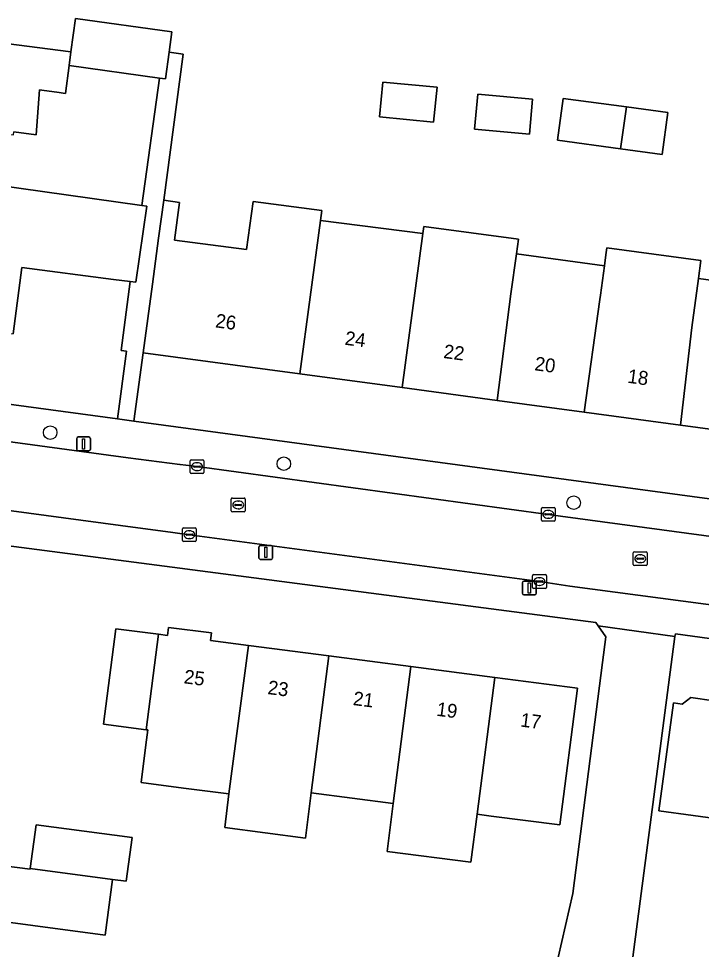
# Model space of a CAD drawing. Extents: x 161258 to 161838, y 380833 to 381727.
# Drawn here: x 161606.8 to 161656.1, y 381558.2 to 381625.4 of the extents above; entities that cross this region are included whole.
import ezdxf

# ---------------------------------------------------------------- set-up
doc = ezdxf.new("R2010")
doc.units = 0
for name, color, linetype in [('IMGEO_Boom', 7, 'Continuous'), ('IMGEO_Erf', 7, 'Continuous'), ('IMGEO_Kolk', 7, 'Continuous'), ('IMGEO_Lichtmast', 7, 'Continuous'), ('IMGEO_Pand', 7, 'Continuous'), ('IMGEO_Pand_nummerreeks', 7, 'Continuous'), ('IMGEO_Rijbaan_lokaal_open', 7, 'Continuous'), ('IMGEO_Rioolput', 7, 'Continuous'), ('IMGEO_Voetpad_open', 7, 'Continuous')]:
    doc.layers.add(name, color=color, linetype=linetype)

msp = doc.modelspace()

# ---------------------------------------------------------------- linework, layer by layer
at = {"layer": 'IMGEO_Boom'}
for centre in [(161609.062, 381595.533), (161625.947, 381593.282), (161646.905, 381590.465)]:
    msp.add_circle(centre, 0.489, dxfattribs=at)
at = {"layer": 'IMGEO_Erf'}
for points in [[(161602.113, 381624.129), (161610.561, 381623.035), (161610.892, 381625.441), (161617.857, 381624.484), (161617.655, 381623.013), (161618.683, 381622.875), (161617.264, 381612.315), (161618.407, 381612.168), (161618.038, 381609.425), (161623.262, 381608.755), (161623.728, 381612.224), (161628.687, 381611.589), (161628.589, 381610.855), (161635.999, 381609.905), (161636.067, 381610.415), (161642.915, 381609.496), (161642.766, 381608.436), (161649.125, 381607.582), (161649.235, 381608.38), (161649.305, 381608.885), (161656.102, 381607.973), (161655.925, 381606.655), (161662.313, 381605.797)], [(161603.185, 381613.687), (161615.69, 381611.935), (161616.956, 381621.146), (161610.425, 381622.043), (161610.173, 381620.039), (161609.999, 381620.062), (161609.713, 381620.099), (161608.452, 381620.262), (161608.278, 381620.285), (161608.036, 381617.043), (161606.432, 381617.251)], [(161590.17, 381599.725), (161613.919, 381596.521), (161614.581, 381601.424), (161614.194, 381601.476), (161614.838, 381606.445), (161613.628, 381606.602), (161607.003, 381607.46), (161606.383, 381602.669)], [(161645.253, 381555.29), (161646.845, 381562.231), (161648.988, 381578.933), (161649.218, 381580.79), (161648.68, 381581.562), (161648.507, 381581.81), (161589.258, 381589.545)], [(161697.263, 381575.097), (161654.253, 381581.004), (161654.227, 381580.806), (161650.995, 381556.159)], [(161658.013, 381567.534), (161653.058, 381568.207), (161654.116, 381576.004), (161654.757, 381575.918), (161655.372, 381576.386), (161657.024, 381576.162)]]:
    msp.add_lwpolyline(points, dxfattribs=at)
for points in [[(161636.78, 381617.972), (161632.856, 381618.353), (161633.099, 381620.861), (161637.023, 381620.48)], [(161639.739, 381617.457), (161639.971, 381619.98), (161643.931, 381619.617), (161643.698, 381617.093)], [(161653.306, 381615.623), (161650.297, 381616.031), (161645.74, 381616.651), (161646.151, 381619.678), (161650.716, 381619.058), (161653.717, 381618.65)], [(161681.773, 381592.431), (161673.908, 381593.488), (161667.735, 381594.317), (161660.894, 381595.236), (161654.633, 381596.076), (161647.661, 381597.013), (161641.376, 381597.857), (161634.504, 381598.78), (161627.101, 381599.774), (161615.784, 381601.294), (161615.118, 381596.359), (161707.085, 381583.95), (161707.511, 381583.893), (161708.709, 381583.729), (161709.752, 381591.347), (161708.256, 381591.548), (161707.903, 381588.922), (161701.922, 381589.725), (161695.354, 381590.607), (161688.066, 381591.586)], [(161621.687, 381566.997), (161621.98, 381569.431), (161618.687, 381569.857), (161615.631, 381570.252), (161615.984, 381572.978), (161616.123, 381574.051), (161615.999, 381574.067), (161612.906, 381574.468), (161613.798, 381581.363), (161616.893, 381580.962), (161617.538, 381580.879), (161617.613, 381581.462), (161620.715, 381581.061), (161620.644, 381580.508), (161623.392, 381580.152), (161629.21, 381579.399), (161635.142, 381578.631), (161641.202, 381577.846), (161647.184, 381577.072), (161645.905, 381567.19), (161640.947, 381567.832), (161639.921, 381567.965), (161639.472, 381564.494), (161633.412, 381565.278), (161633.861, 381568.749), (161627.93, 381569.517), (161627.506, 381566.244)], [(161602.559, 381560.618), (161603.084, 381564.583), (161607.608, 381563.983), (161607.615, 381564.037), (161608.035, 381567.205), (161614.975, 381566.286), (161614.563, 381563.116), (161613.567, 381563.248), (161613.045, 381559.228)]]:
    msp.add_lwpolyline(points, close=True, dxfattribs=at)
at = {"layer": 'IMGEO_Kolk'}
for p, q in [((161619.174, 381592.648), (161619.174, 381593.5)), ((161619.249, 381593.574), (161620.101, 381593.574)), ((161619.662, 381593.354), (161619.687, 381593.354)), ((161620.175, 381593.5), (161620.175, 381592.648)), ((161619.433, 381593.068), (161619.433, 381593.08)), ((161619.871, 381593.031), (161619.473, 381593.031)), ((161619.476, 381593.117), (161619.874, 381593.117)), ((161619.685, 381592.794), (161619.66, 381592.794)), ((161619.917, 381593.08), (161619.917, 381593.068)), ((161620.101, 381592.574), (161619.249, 381592.574)), ((161644.57, 381589.201), (161644.57, 381590.053)), ((161644.645, 381590.127), (161645.497, 381590.127)), ((161645.058, 381589.907), (161645.083, 381589.907)), ((161645.571, 381590.053), (161645.571, 381589.201)), ((161644.829, 381589.621), (161644.829, 381589.633)), ((161645.267, 381589.584), (161644.869, 381589.584)), ((161644.872, 381589.67), (161645.27, 381589.67)), ((161645.081, 381589.347), (161645.056, 381589.347)), ((161645.313, 381589.633), (161645.313, 381589.621)), ((161618.621, 381587.731), (161618.621, 381588.583)), ((161618.696, 381588.657), (161619.548, 381588.657)), ((161619.622, 381588.583), (161619.622, 381587.731)), ((161645.497, 381589.127), (161644.645, 381589.127)), ((161618.88, 381588.151), (161618.88, 381588.163)), ((161619.318, 381588.114), (161618.92, 381588.114)), ((161618.923, 381588.2), (161619.321, 381588.2)), ((161619.109, 381588.437), (161619.134, 381588.437)), ((161619.364, 381588.163), (161619.364, 381588.151)), ((161619.548, 381587.657), (161618.696, 381587.657)), ((161619.132, 381587.877), (161619.107, 381587.877)), ((161643.928, 381584.345), (161643.928, 381585.197)), ((161644.003, 381585.271), (161644.855, 381585.271)), ((161644.929, 381585.197), (161644.929, 381584.345)), ((161644.187, 381584.765), (161644.187, 381584.777)), ((161644.625, 381584.728), (161644.227, 381584.728)), ((161644.23, 381584.814), (161644.628, 381584.814)), ((161644.416, 381585.051), (161644.441, 381585.051)), ((161644.671, 381584.777), (161644.671, 381584.765)), ((161644.855, 381584.271), (161644.003, 381584.271)), ((161644.439, 381584.491), (161644.414, 381584.491))]:
    msp.add_line(p, q, dxfattribs=at)
for points in [[(161619.174, 381592.648), (161619.174, 381593.5)], [(161619.249, 381593.574), (161620.101, 381593.574)], [(161620.175, 381593.5), (161620.175, 381592.648)], [(161620.101, 381592.574), (161619.249, 381592.574)], [(161644.57, 381589.201), (161644.57, 381590.053)], [(161644.645, 381590.127), (161645.497, 381590.127)], [(161645.571, 381590.053), (161645.571, 381589.201)], [(161618.621, 381587.731), (161618.621, 381588.583)], [(161618.696, 381588.657), (161619.548, 381588.657)], [(161619.622, 381588.583), (161619.622, 381587.731)], [(161645.497, 381589.127), (161644.645, 381589.127)], [(161619.548, 381587.657), (161618.696, 381587.657)], [(161643.928, 381584.345), (161643.928, 381585.197)], [(161644.003, 381585.271), (161644.855, 381585.271)], [(161644.929, 381585.197), (161644.929, 381584.345)], [(161644.855, 381584.271), (161644.003, 381584.271)]]:
    msp.add_lwpolyline(points, dxfattribs=at)
for centre, radius, start, end in [((161619.251, 381593.498), 0.0765, 91.55205, 178.44795), ((161619.251, 381593.498), 0.0765, 91.55205, 178.44795), ((161620.099, 381593.498), 0.0765, 1.55205, 88.44795), ((161620.099, 381593.498), 0.0765, 1.55205, 88.44795), ((161619.251, 381592.65), 0.0765, 181.55205, 268.44795), ((161619.251, 381592.65), 0.0765, 181.55205, 268.44795), ((161619.473, 381593.077), 0.0403, 85.87752, 175.75265), ((161619.47, 381593.067), 0.0366, 178.93798, 274.71019), ((161619.874, 381593.074), 0.043, 264.86636, 352.45326), ((161619.878, 381593.079), 0.0386, 1.73085, 96.63898), ((161620.099, 381592.65), 0.0765, 271.55205, 358.44795), ((161620.099, 381592.65), 0.0765, 271.55205, 358.44795), ((161644.647, 381590.051), 0.0765, 91.55205, 178.44795), ((161644.647, 381590.051), 0.0765, 91.55205, 178.44795), ((161645.495, 381590.051), 0.0765, 1.55205, 88.44795), ((161645.495, 381590.051), 0.0765, 1.55205, 88.44795), ((161644.869, 381589.63), 0.0403, 85.87752, 175.75265), ((161644.866, 381589.62), 0.0366, 178.93798, 274.71019), ((161645.27, 381589.627), 0.043, 264.86636, 352.45326), ((161645.274, 381589.632), 0.0386, 1.73085, 96.63898), ((161618.698, 381588.581), 0.0765, 91.55205, 178.44795), ((161618.698, 381588.581), 0.0765, 91.55205, 178.44795), ((161619.546, 381588.581), 0.0765, 1.55205, 88.44795), ((161619.546, 381588.581), 0.0765, 1.55205, 88.44795), ((161644.647, 381589.203), 0.0765, 181.55205, 268.44795), ((161644.647, 381589.203), 0.0765, 181.55205, 268.44795), ((161645.495, 381589.203), 0.0765, 271.55205, 358.44795), ((161645.495, 381589.203), 0.0765, 271.55205, 358.44795), ((161618.92, 381588.16), 0.0403, 85.87752, 175.75265), ((161618.917, 381588.15), 0.0366, 178.93798, 274.71019), ((161619.321, 381588.157), 0.043, 264.86636, 352.45326), ((161619.325, 381588.162), 0.0386, 1.73085, 96.63898), ((161618.698, 381587.733), 0.0765, 181.55205, 268.44795), ((161618.698, 381587.733), 0.0765, 181.55205, 268.44795), ((161619.546, 381587.733), 0.0765, 271.55205, 358.44795), ((161619.546, 381587.733), 0.0765, 271.55205, 358.44795), ((161644.005, 381585.195), 0.0765, 91.55205, 178.44795), ((161644.005, 381585.195), 0.0765, 91.55205, 178.44795), ((161644.853, 381585.195), 0.0765, 1.55205, 88.44795), ((161644.853, 381585.195), 0.0765, 1.55205, 88.44795), ((161644.227, 381584.774), 0.0403, 85.87752, 175.75265), ((161644.224, 381584.764), 0.0366, 178.93798, 274.71019), ((161644.628, 381584.771), 0.043, 264.86636, 352.45326), ((161644.632, 381584.776), 0.0386, 1.73085, 96.63898), ((161644.005, 381584.347), 0.0765, 181.55205, 268.44795), ((161644.005, 381584.347), 0.0765, 181.55205, 268.44795), ((161644.853, 381584.347), 0.0765, 271.55205, 358.44795), ((161644.853, 381584.347), 0.0765, 271.55205, 358.44795)]:
    msp.add_arc(centre, radius, start, end, dxfattribs=at)
for centre, major_axis, ratio, start_param, end_param in [((161619.661, 381593.074), (-0.387, 0.002), 0.722429, 4.712389, 7.853982), ((161619.686, 381593.074), (-0.39, 0.002), 0.717154, 1.570796, 4.712389), ((161645.057, 381589.627), (-0.387, 0.002), 0.722429, 4.712389, 7.853982), ((161645.082, 381589.627), (-0.39, 0.002), 0.717154, 1.570796, 4.712389), ((161619.108, 381588.157), (-0.387, 0.002), 0.722429, 4.712389, 7.853982), ((161619.133, 381588.157), (-0.39, 0.002), 0.717154, 1.570796, 4.712389), ((161644.415, 381584.771), (-0.387, 0.002), 0.722429, 4.712389, 7.853982), ((161644.44, 381584.771), (-0.39, 0.002), 0.717154, 1.570796, 4.712389)]:
    msp.add_ellipse(centre, major_axis=major_axis, ratio=ratio, start_param=start_param, end_param=end_param, dxfattribs=at)
at = {"layer": 'IMGEO_Lichtmast'}
for p, q in [((161610.975, 381594.318), (161610.975, 381595.118)), ((161610.975, 381595.118), (161610.975, 381594.318)), ((161611.075, 381595.218), (161611.865, 381595.218)), ((161611.865, 381595.218), (161611.075, 381595.218)), ((161611.965, 381595.118), (161611.965, 381594.318)), ((161611.965, 381594.318), (161611.965, 381595.118)), ((161611.865, 381594.218), (161611.075, 381594.218)), ((161611.075, 381594.218), (161611.865, 381594.218)), ((161624.151, 381586.473), (161624.151, 381587.273)), ((161624.151, 381587.273), (161624.151, 381586.473)), ((161624.251, 381587.373), (161625.041, 381587.373)), ((161625.041, 381587.373), (161624.251, 381587.373)), ((161625.141, 381587.273), (161625.141, 381586.473)), ((161625.141, 381586.473), (161625.141, 381587.273)), ((161625.041, 381586.373), (161624.251, 381586.373)), ((161624.251, 381586.373), (161625.041, 381586.373)), ((161643.204, 381583.906), (161643.204, 381584.706)), ((161643.204, 381584.706), (161643.204, 381583.906)), ((161643.304, 381584.806), (161644.094, 381584.806)), ((161644.094, 381584.806), (161643.304, 381584.806)), ((161644.194, 381584.706), (161644.194, 381583.906)), ((161644.194, 381583.906), (161644.194, 381584.706)), ((161644.094, 381583.806), (161643.304, 381583.806)), ((161643.304, 381583.806), (161644.094, 381583.806))]:
    msp.add_line(p, q, dxfattribs=at)
for points in [[(161611.395, 381595.093), (161611.545, 381595.093), (161611.545, 381594.343), (161611.395, 381594.343), (161611.395, 381595.093)], [(161624.571, 381587.248), (161624.721, 381587.248), (161624.721, 381586.498), (161624.571, 381586.498), (161624.571, 381587.248)], [(161643.624, 381584.681), (161643.774, 381584.681), (161643.774, 381583.931), (161643.624, 381583.931), (161643.624, 381584.681)]]:
    msp.add_lwpolyline(points, dxfattribs=at)
for centre, start, end in [((161611.075, 381595.118), 90, 180), ((161611.075, 381595.118), 90, 180), ((161611.865, 381595.118), 0, 90), ((161611.865, 381595.118), 360, 90), ((161611.075, 381594.318), 180, 270), ((161611.075, 381594.318), 180, 270), ((161611.865, 381594.318), 270, 0), ((161611.865, 381594.318), 270, 0), ((161624.251, 381587.273), 90, 180), ((161624.251, 381587.273), 90, 180), ((161625.041, 381587.273), 0, 90), ((161625.041, 381587.273), 360, 90), ((161624.251, 381586.473), 180, 270), ((161624.251, 381586.473), 180, 270), ((161625.041, 381586.473), 270, 0), ((161625.041, 381586.473), 270, 0), ((161643.304, 381584.706), 90, 180), ((161643.304, 381584.706), 90, 180), ((161644.094, 381584.706), 0, 90), ((161644.094, 381584.706), 360, 90), ((161643.304, 381583.906), 180, 270), ((161643.304, 381583.906), 180, 270), ((161644.094, 381583.906), 270, 0), ((161644.094, 381583.906), 270, 0)]:
    msp.add_arc(centre, 0.1, start, end, dxfattribs=at)
at = {"layer": 'IMGEO_Pand'}
for points in [[(161617.857, 381624.484), (161610.892, 381625.441), (161610.561, 381623.035), (161610.425, 381622.043), (161616.956, 381621.146), (161617.39, 381621.086), (161617.655, 381623.013)], [(161610.425, 381622.043), (161610.561, 381623.035), (161602.113, 381624.129), (161597.154, 381624.772), (161596.323, 381618.351), (161601.282, 381617.709), (161606.405, 381617.045), (161606.432, 381617.251), (161608.036, 381617.043), (161608.278, 381620.285), (161608.452, 381620.262), (161609.713, 381620.099), (161609.999, 381620.062), (161610.173, 381620.039)], [(161632.856, 381618.353), (161636.78, 381617.972), (161637.023, 381620.48), (161633.099, 381620.861)], [(161639.739, 381617.457), (161643.698, 381617.093), (161643.931, 381619.617), (161639.971, 381619.98)], [(161650.297, 381616.031), (161650.716, 381619.058), (161646.151, 381619.678), (161645.74, 381616.651)], [(161650.297, 381616.031), (161653.306, 381615.623), (161653.717, 381618.65), (161650.716, 381619.058)], [(161607.003, 381607.46), (161613.628, 381606.602), (161614.838, 381606.445), (161615.239, 381606.393), (161616.042, 381611.886), (161615.69, 381611.935), (161603.185, 381613.687), (161602.69, 381610.158), (161600.364, 381610.459), (161595.411, 381611.1), (161594.523, 381604.235), (161595.666, 381604.087), (161595.584, 381603.454), (161598.109, 381603.127), (161598.187, 381603.731), (161603.711, 381603.016), (161606.383, 381602.669)], [(161628.589, 381610.855), (161628.687, 381611.589), (161623.728, 381612.224), (161623.262, 381608.755), (161618.038, 381609.425), (161618.407, 381612.168), (161617.264, 381612.315), (161616.896, 381609.571), (161616.45, 381606.25), (161615.784, 381601.294), (161627.101, 381599.774)], [(161634.504, 381598.78), (161635.999, 381609.905), (161628.589, 381610.855), (161627.101, 381599.774)], [(161634.504, 381598.78), (161641.376, 381597.857), (161642.362, 381605.56), (161642.766, 381608.436), (161642.915, 381609.496), (161636.067, 381610.415), (161635.999, 381609.905)], [(161655.452, 381603.137), (161655.925, 381606.655), (161656.102, 381607.973), (161649.305, 381608.885), (161649.235, 381608.38), (161649.125, 381607.582), (161648.831, 381605.455), (161648.79, 381605.16), (161647.661, 381597.013), (161654.633, 381596.076)], [(161648.79, 381605.16), (161648.831, 381605.455), (161649.125, 381607.582), (161642.766, 381608.436), (161642.362, 381605.56), (161641.376, 381597.857), (161647.661, 381597.013)], [(161662.062, 381603.929), (161662.313, 381605.797), (161655.925, 381606.655), (161655.452, 381603.137), (161654.633, 381596.076), (161660.894, 381595.236)], [(161615.999, 381574.067), (161616.893, 381580.962), (161613.798, 381581.363), (161612.906, 381574.468)], [(161615.999, 381574.067), (161616.123, 381574.051), (161615.984, 381572.978), (161615.631, 381570.252), (161618.687, 381569.857), (161621.98, 381569.431), (161623.392, 381580.152), (161620.644, 381580.508), (161620.715, 381581.061), (161617.613, 381581.462), (161617.538, 381580.879), (161616.893, 381580.962)], [(161627.93, 381569.517), (161629.21, 381579.399), (161623.392, 381580.152), (161621.98, 381569.431), (161621.687, 381566.997), (161627.506, 381566.244)], [(161627.93, 381569.517), (161633.861, 381568.749), (161635.142, 381578.631), (161629.21, 381579.399)], [(161641.202, 381577.846), (161635.142, 381578.631), (161633.861, 381568.749), (161633.412, 381565.278), (161639.472, 381564.494), (161639.921, 381567.965)], [(161639.921, 381567.965), (161640.947, 381567.832), (161645.905, 381567.19), (161647.184, 381577.072), (161641.202, 381577.846)], [(161660.285, 381575.137), (161657.518, 381575.512), (161657.024, 381576.162), (161655.372, 381576.386), (161654.757, 381575.918), (161654.116, 381576.004), (161653.058, 381568.207), (161658.013, 381567.534), (161659.232, 381567.369)], [(161613.567, 381563.248), (161614.563, 381563.116), (161614.975, 381566.286), (161608.035, 381567.205), (161607.615, 381564.037)], [(161613.567, 381563.248), (161607.615, 381564.037), (161607.608, 381563.983), (161603.084, 381564.583), (161602.559, 381560.618), (161613.045, 381559.228)]]:
    msp.add_lwpolyline(points, close=True, dxfattribs=at)
at = {"layer": 'IMGEO_Rijbaan_lokaal_open'}
for points in [[(161723.791, 381579.08), (161713.619, 381580.431), (161707.156, 381581.295), (161706.756, 381581.348), (161684.368, 381584.359), (161663.266, 381587.166), (161645.071, 381589.627), (161619.675, 381593.074), (161618.458, 381593.224), (161618.426, 381593.228), (161614.689, 381593.717), (161591.61, 381596.833)], [(161591.008, 381591.931), (161614.153, 381588.812), (161617.916, 381588.319), (161619.122, 381588.157), (161644.429, 381584.771), (161646.629, 381584.448), (161656.447, 381583.147), (161662.594, 381582.337), (161683.665, 381579.482), (161697.6, 381577.592), (161697.62, 381577.589), (161697.936, 381577.548), (161704.805, 381576.659), (161705.23, 381576.604), (161705.253, 381576.601), (161706.214, 381576.473), (161723.234, 381574.173)], [(161650.995, 381556.159), (161654.227, 381580.806), (161648.68, 381581.562), (161649.218, 381580.79), (161648.988, 381578.933), (161646.845, 381562.231), (161645.253, 381555.29)]]:
    msp.add_lwpolyline(points, dxfattribs=at)
at = {"layer": 'IMGEO_Rioolput'}
for p, q in [((161622.154, 381589.881), (161622.154, 381590.733)), ((161622.229, 381590.807), (161623.081, 381590.807)), ((161622.642, 381590.587), (161622.667, 381590.587)), ((161623.155, 381590.733), (161623.155, 381589.881)), ((161622.413, 381590.301), (161622.413, 381590.313)), ((161622.851, 381590.264), (161622.453, 381590.264)), ((161622.456, 381590.35), (161622.854, 381590.35)), ((161622.665, 381590.027), (161622.64, 381590.027)), ((161622.897, 381590.313), (161622.897, 381590.301)), ((161623.081, 381589.807), (161622.229, 381589.807)), ((161651.214, 381585.997), (161651.214, 381586.849)), ((161651.289, 381586.923), (161652.141, 381586.923)), ((161651.702, 381586.703), (161651.727, 381586.703)), ((161652.215, 381586.849), (161652.215, 381585.997)), ((161652.141, 381585.923), (161651.289, 381585.923)), ((161651.473, 381586.417), (161651.473, 381586.429)), ((161651.911, 381586.38), (161651.513, 381586.38)), ((161651.516, 381586.466), (161651.914, 381586.466)), ((161651.725, 381586.143), (161651.7, 381586.143)), ((161651.957, 381586.429), (161651.957, 381586.417))]:
    msp.add_line(p, q, dxfattribs=at)
for points in [[(161622.154, 381589.881), (161622.154, 381590.733)], [(161622.229, 381590.807), (161623.081, 381590.807)], [(161623.155, 381590.733), (161623.155, 381589.881)], [(161623.081, 381589.807), (161622.229, 381589.807)], [(161651.214, 381585.997), (161651.214, 381586.849)], [(161651.289, 381586.923), (161652.141, 381586.923)], [(161652.215, 381586.849), (161652.215, 381585.997)], [(161652.141, 381585.923), (161651.289, 381585.923)]]:
    msp.add_lwpolyline(points, dxfattribs=at)
for centre, radius, start, end in [((161622.231, 381590.731), 0.0765, 91.55205, 178.44795), ((161622.231, 381590.731), 0.0765, 91.55205, 178.44795), ((161623.079, 381590.731), 0.0765, 1.55205, 88.44795), ((161623.079, 381590.731), 0.0765, 1.55205, 88.44795), ((161622.453, 381590.31), 0.0403, 85.87752, 175.75265), ((161622.45, 381590.3), 0.0366, 178.93798, 274.71019), ((161622.854, 381590.307), 0.043, 264.86636, 352.45326), ((161622.858, 381590.312), 0.0386, 1.73085, 96.63898), ((161622.231, 381589.883), 0.0765, 181.55205, 268.44795), ((161622.231, 381589.883), 0.0765, 181.55205, 268.44795), ((161623.079, 381589.883), 0.0765, 271.55205, 358.44795), ((161623.079, 381589.883), 0.0765, 271.55205, 358.44795), ((161651.291, 381586.847), 0.0765, 91.55205, 178.44795), ((161651.291, 381586.847), 0.0765, 91.55205, 178.44795), ((161652.139, 381586.847), 0.0765, 1.55205, 88.44795), ((161652.139, 381586.847), 0.0765, 1.55205, 88.44795), ((161651.291, 381585.999), 0.0765, 181.55205, 268.44795), ((161651.291, 381585.999), 0.0765, 181.55205, 268.44795), ((161651.513, 381586.426), 0.0403, 85.87752, 175.75265), ((161651.51, 381586.416), 0.0366, 178.93798, 274.71019), ((161651.914, 381586.423), 0.043, 264.86636, 352.45326), ((161651.918, 381586.428), 0.0386, 1.73085, 96.63898), ((161652.139, 381585.999), 0.0765, 271.55205, 358.44795), ((161652.139, 381585.999), 0.0765, 271.55205, 358.44795)]:
    msp.add_arc(centre, radius, start, end, dxfattribs=at)
for centre, major_axis, ratio, start_param, end_param in [((161622.641, 381590.307), (-0.387, 0.002), 0.722429, 4.712389, 7.853982), ((161622.666, 381590.307), (-0.39, 0.002), 0.717154, 1.570796, 4.712389), ((161651.701, 381586.423), (-0.387, 0.002), 0.722429, 4.712389, 7.853982), ((161651.726, 381586.423), (-0.39, 0.002), 0.717154, 1.570796, 4.712389)]:
    msp.add_ellipse(centre, major_axis=major_axis, ratio=ratio, start_param=start_param, end_param=end_param, dxfattribs=at)
at = {"layer": 'IMGEO_Voetpad_open'}
for points in [[(161617.655, 381623.013), (161617.39, 381621.086), (161616.956, 381621.146), (161615.69, 381611.935), (161616.042, 381611.886), (161615.239, 381606.393), (161614.838, 381606.445), (161614.194, 381601.476), (161614.581, 381601.424), (161613.919, 381596.521), (161615.118, 381596.359), (161615.784, 381601.294), (161616.45, 381606.25), (161616.896, 381609.571), (161617.264, 381612.315), (161618.683, 381622.875)], [(161615.118, 381596.359), (161613.919, 381596.521), (161590.17, 381599.725), (161590.41, 381597.026), (161590.506, 381597.003), (161590.603, 381596.979), (161591.3, 381596.865), (161591.61, 381596.833), (161614.689, 381593.717), (161618.426, 381593.228), (161618.458, 381593.224), (161619.675, 381593.074), (161645.071, 381589.627), (161663.266, 381587.166), (161684.368, 381584.359), (161706.756, 381581.348), (161707.156, 381581.295), (161707.511, 381583.893), (161707.085, 381583.95)]]:
    msp.add_lwpolyline(points, close=True, dxfattribs=at)
for points in [[(161646.629, 381584.448), (161644.429, 381584.771), (161619.122, 381588.157), (161617.916, 381588.319), (161614.153, 381588.812), (161591.008, 381591.931), (161589.798, 381592.101), (161589.764, 381592.108), (161589.729, 381592.114)], [(161589.258, 381589.545), (161648.507, 381581.81), (161648.68, 381581.562), (161654.227, 381580.806), (161654.253, 381581.004), (161697.263, 381575.097), (161697.567, 381575.055), (161697.936, 381577.548), (161697.62, 381577.589), (161697.6, 381577.592), (161683.665, 381579.482), (161662.594, 381582.337), (161656.447, 381583.147), (161646.629, 381584.448)]]:
    msp.add_lwpolyline(points, dxfattribs=at)

# ---------------------------------------------------------------- texts
at = {"layer": 'IMGEO_Pand_nummerreeks'}
for s, rotation, p in [('26', 352.35101, (161620.96, 381603.141)), ('24', 352.35069, (161630.319, 381601.885)), ('22', 352.35069, (161637.453, 381600.927)), ('20', 352.35101, (161644.039, 381600.041)), ('18', 352.35101, (161650.757, 381599.139)), ('25', 352.6812, (161618.685, 381577.426)), ('23', 352.6812, (161624.743, 381576.648)), ('21', 352.6812, (161630.913, 381575.855)), ('19', 352.6812, (161636.949, 381575.08)), ('17', 352.6812, (161643.007, 381574.302))]:
    msp.add_text(s, height=1, rotation=rotation, dxfattribs=at).set_placement(p)

doc.saveas('drawing.dxf')
